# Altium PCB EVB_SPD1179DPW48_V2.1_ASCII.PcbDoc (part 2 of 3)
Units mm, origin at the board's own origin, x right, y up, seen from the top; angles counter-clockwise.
Board outline 135 x 90 mm, 4 copper layers (Top Layer, GND, L3, Bottom Layer), stack 0.603 mm thick; 322 components, 156 nets, 727 pads, 939 vias.
Unrouted connection lines stored in the file: 172.
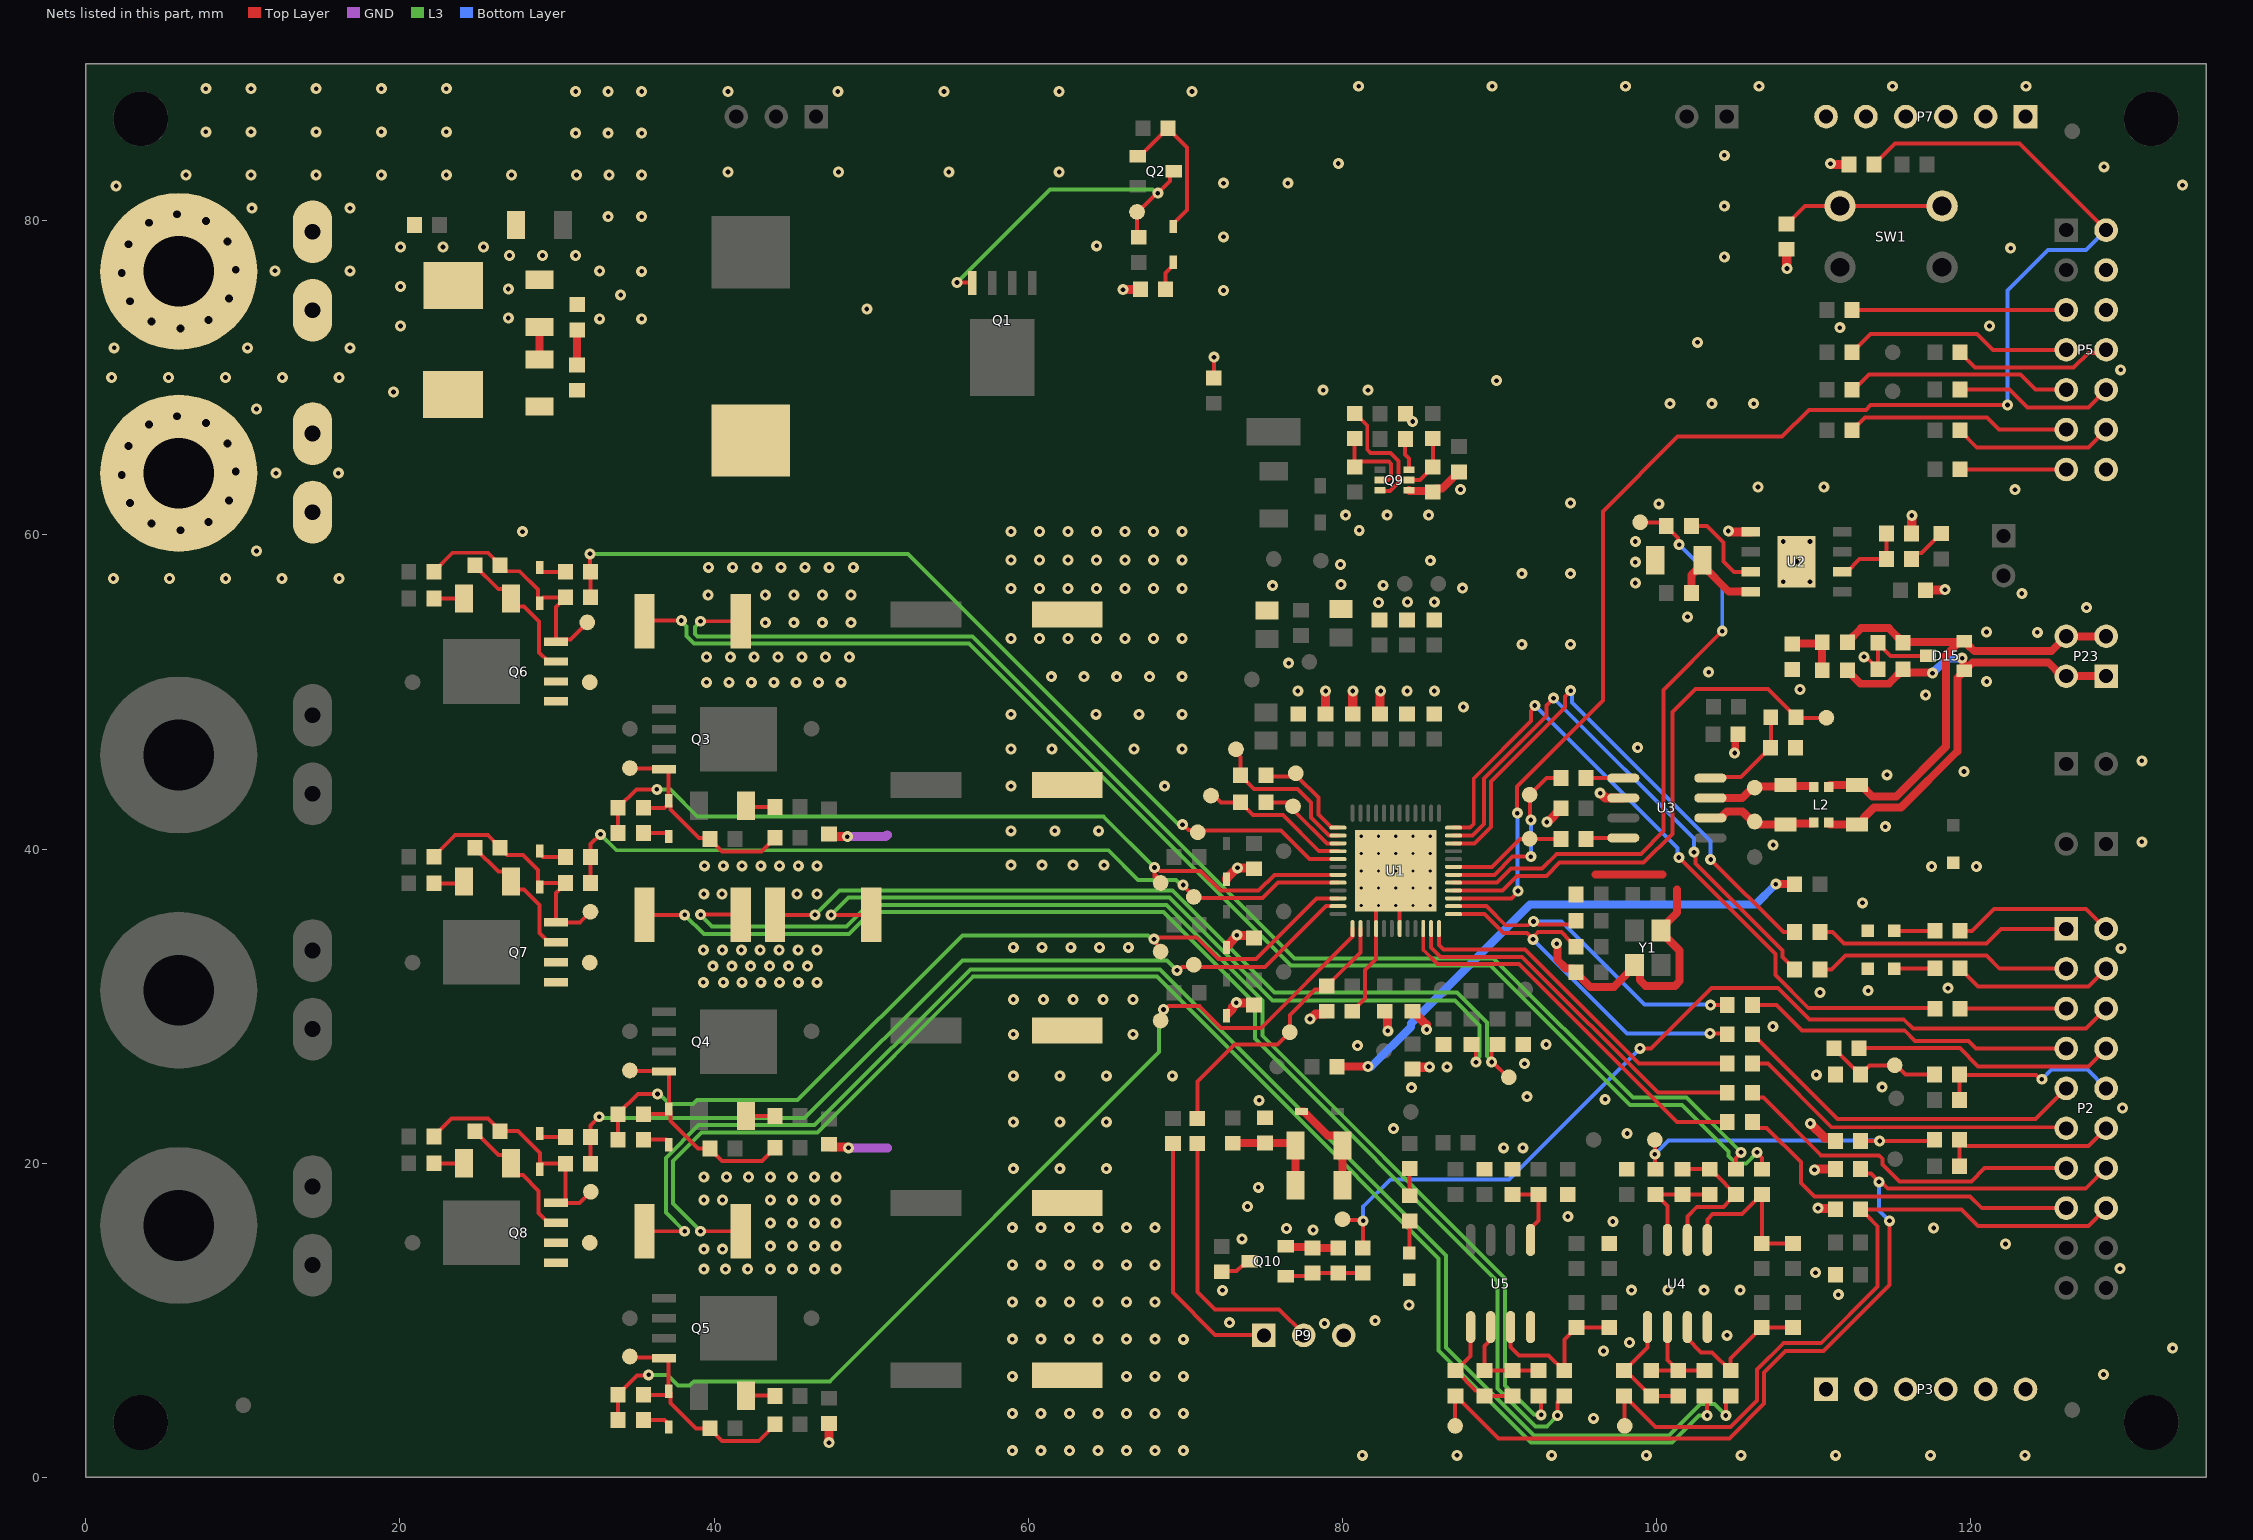
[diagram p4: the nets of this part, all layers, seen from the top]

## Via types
v1: diameter 0.7, hole 0.3, Top Layer to Bottom Layer, tented both sides, 693 vias
v2: diameter 0.5, hole 0.2, Top Layer to Bottom Layer, tented both sides, 154 vias
v3: diameter 0.9, hole 0.5, Top Layer to Bottom Layer, 60 vias
v4: diameter 0.5, hole 0.2, Top Layer to Bottom Layer, 32 vias

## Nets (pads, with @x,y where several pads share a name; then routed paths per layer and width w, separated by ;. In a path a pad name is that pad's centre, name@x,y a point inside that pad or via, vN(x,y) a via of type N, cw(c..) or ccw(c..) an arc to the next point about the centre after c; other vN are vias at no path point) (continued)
ADC0: R30.2 U1.46 | length 25.2
  Top Layer w0.254: U1.46@85.152,34.941 85.152,33.593 86.06,32.685 91.255,32.685 101.309,22.631 R30.2@104.508,22.631
ADC1: R29.2 U1.47 | length 23.9
  Top Layer w0.254: U1.47@85.652,34.941 85.652,33.74 86.249,33.142 91.445,33.142 100.095,24.492 R29.2@104.508,24.492
ADC2: R28.2 U1.48 | length 22.5
  Top Layer w0.254: U1.48@86.152,34.941 86.152,33.887 86.439,33.6 91.634,33.6 98.881,26.352 R28.2@104.508,26.352
ADC3: R1.2 R10.2 U1.1 | length 24
  Top Layer w0.254: U1.1@87.077,35.866 89.04,35.866 90.26,34.646 91.747,34.646 v1(92.135,34.258) 92.152,34.275 92.152,34.402 92.472,34.722 93.942,34.722 94.509,34.155 94.534,34.155 94.882,33.807 R1.2@94.882,33.782 ; v1(103.403,28.27) 104.451,28.27 R10.2@104.508,28.213
  Bottom Layer w0.254: v1(92.135,34.258) 98.122,28.27 v1(103.403,28.27)
ADC4: R8.2 R120.2 U1.2 | length 23.3
  Top Layer w0.254: U1.2@87.077,36.366 89.186,36.366 90.399,35.154 91.815,35.154 92.049,35.387 v1(92.17,35.387) ; v1@92.07,35.387 92.253,35.204 92.35,35.302 92.376,35.302 92.473,35.204 94.653,35.204 R120.2@94.882,35.433 ; v1(103.438,30.065) 104.5,30.065 R8.2@104.508,30.074
  Bottom Layer w0.254: v1(92.17,35.387) 93.95,35.387 99.238,30.099 103.403,30.099 v1(103.438,30.065)
BOOT: P5.2 R11.2 U1.3 | length 91.7
  Top Layer w0.254: U1.3@87.5,36.866 90.765,36.866 91.186,37.287 v1(91.186,37.332) ; v1(91.142,42.291) 91.118,42.315 91.118,43.989 96.585,49.456 96.585,61.509 101.344,66.269 108.001,66.269 109.703,67.97 113.334,67.97 113.639,68.275 v1(122.352,68.275) ; R11.2@113.855,83.591 115.194,84.93 123.106,84.93 P5.2@128.626,79.41
  Bottom Layer w0.254: v1(91.142,42.291) 91.142,37.376 v1(91.186,37.332) ; v1(122.352,68.275) 122.352,75.565 124.917,78.13 127.346,78.13 P5.2@128.626,79.41
CANH: CANH.1 L2.1 R59.1 U3.7 | length 7
  Top Layer w0.508: U3.7@103.433,43.256 105.455,43.256 106.194,43.995 108.13,43.995 L2.1@108.209,44.074 108.266,44.018 109.969,44.018 110.01,43.977 R59.1@110.01,43.961
CANL: CANL.1 L2.2 R67.1 U3.6 | length 6.8
  Top Layer w0.508: U3.6@103.433,41.986 104.14,41.986 104.177,42.023 104.177,42.07 104.499,42.393 105.48,42.393 106.115,41.758 CANL.1@106.248,41.758 ; CANL.1@106.564,41.575 L2.2@108.209,41.575 108.266,41.631 109.969,41.631 110.01,41.672 R67.1@110.01,41.688
CANLDOEN: CANLDOEN.1 R81.1 U1.5 | length 39
  Top Layer w0.254: U1.5@87.077,37.866 89.832,37.866 90.727,38.76 92.71,38.76 93.65,39.701 99.01,39.701 100.457,41.148 100.457,50.145 v1(104.188,53.876) ; CANLDOEN.1@98.958,60.808 100.394,60.808 R81.1@100.622,60.579 100.622,60.554 101.362,59.814 101.362,59.471 v1(101.448,59.385)
  Bottom Layer w0.254: v1(101.448,59.385) 104.188,56.645 v1(104.188,53.876)
CANRX: CANRX.1 R65.2 U1.7 | length 7.6
  Top Layer w0.254: U1.7@87.077,38.866 89.539,38.866 91.313,40.64 R65.2@93.917,40.64
CANSTB: CANSTB.1 R79.1 U1.4 | length 34.4
  Top Layer w0.254: U1.4@87.077,37.366 90.186,37.366 91.123,38.303 92.989,38.303 93.828,39.141 99.187,39.141 101.016,40.97 101.016,48.717 102.489,50.19 107.099,50.19 108.877,48.412 R79.1@108.877,48.387 108.902,48.362 CANSTB.1@110.82,48.362
CANTX: CANTX.1 R62.2 U1.6 | length 11.8
  Top Layer w0.254: U1.6@87.077,38.366 89.686,38.366 90.842,39.522 v1(91.999,39.522) ; v1(91.999,41.859) 91.961,41.897 91.961,43.396 91.91,43.447 92.989,44.526 R62.2@93.917,44.526
  Bottom Layer w0.254: v1(91.999,39.522) v1(91.999,41.859)
CFBOT0: C50.1 CFBOT0.1 U1.26 | length 10.1
  Top Layer w0.254: CFBOT0.1@73.228,46.355 73.228,46.153 73.53,45.852 C50.1@73.53,44.704 73.53,44.679 74.386,43.823 77.149,43.823 78.013,42.959 78.013,42.012 79.157,40.868 79.725,40.868 U1.26@79.727,40.866
CFBOT1: C45.2 CFBOT1.1 U1.28 | length 9.6
  Top Layer w0.254: CFBOT1.1@71.637,43.409 71.839,43.409 72.271,42.977 C45.2@73.53,42.977 73.53,42.952 74.31,42.172 76.222,42.172 78.528,39.866 U1.28@79.727,39.866
CFTOP0: C50.2 CFTOP0.1 U1.25 | length 6.6
  Top Layer w0.254: C50.2@75.13,44.704 75.206,44.628 77.124,44.628 78.47,43.282 78.47,42.202 79.306,41.366 U1.25@79.727,41.366
CFTOP1: C45.1 CFTOP1.1 U1.27 | length 5.8
  Top Layer w0.254: C45.1@75.13,42.977 76.602,42.977 77.059,42.52 77.003,42.464 77.003,42.375 79.01,40.368 79.725,40.368 U1.27@79.727,40.366
D2SOUT: P2.8 R122.2 | length 16.7
  Top Layer w0.254: R122.2@112.89,27.33 119.318,27.33 120.474,26.174 127.495,26.174 P2.8@128.626,27.305
FB: R56.1 R57.2 U2.2 | length 4.8
  Top Layer w0.254: U2.2@111.823,57.658 112.123,57.658 112.936,58.471 R56.1@114.643,58.471 R57.2@114.643,60.096
GND: C1.2 C2.1 C5.2 C6.2 C7.1 C8.1 C10.2 C11.1 C12.1 C13.1 C14.2 C15.2 C16.1 C17.1 C18.1 C19.1 C23.1 C24.1 C29.1 C30.1 C31.1 C32.1 C33.1 C34.1 C35.1 C36.1 C37.1 C38.1 C39.1 C40.1 C41.1 C44.1 C52.1 C53.1 C54.1 C55.1 C57.1 C58.1 C61.1 C62.1 C63.1 C64.1 C70.1 C71.1 C72.1 C73.1 C74.1 C77.1 C78.1 C80.1 C81.1 C83.1 C84.1 C90.1 D1.1 D3.2 D4.2 D5.2 D13.2 D14.2 D15.3 D17.2 D18.1 P3.1 P3.2 P3.3 P3.4 P3.5 P3.6 P5.4 P5.6 P5.14 P6.1 P7.1 P7.2 P7.3 P7.4 P7.5 P7.6 P9.3 pad.1@5.918,76.784 Q9.1 Q10.2 R7.1 R9.2 R11.1 R55.1 R57.1 R58.1 R61.1 R85.2 R94.1 R98.2 R99.1 R109.2 U1.40 U1.43 U1.49 U2.5 U2.9 U3.2 U4.4 U5.4 Y1.2 Y1.4 | length 139.4
  Top Layer w0.254: v1(47.459,35.808) 50,35.808 R55.1@50.005,35.814 ; R109.2@71.806,69.99 71.831,70.015 v1(71.831,71.323) ; C78.1@80.629,29.68 80.654,29.68 81.002,30.028 81.002,30.053 81.442,30.493 81.442,32.309 82.152,33.019 U1.40@82.152,34.941 82.152,36.266 v4(82.302,36.416) ; v4(83.402,36.416) 83.652,36.166 U1.43@83.652,34.941 ; R98.2@84.01,67.716 84.482,67.245 v1(84.482,67.22) ; R58.1@88.224,27.572 88.519,27.276 88.516,27.274 v1(88.516,26.44) ; v1(113.208,52.248) 113.293,52.162 113.42,52.162 C62.1@114.097,51.485 ; C62.1@114.097,51.46 C62.1@114.097,51.485 ; C54.1@114.097,53.137 C54.1@114.097,53.112 ; D15.3@117.29,52.299 114.91,52.299 C54.1@114.097,53.112 ; C62.1@114.097,51.485 C54.1@114.097,53.112
  Top Layer w0.508: Q10.2@76.403,14.719 76.46,14.662 78.048,14.662 C80.1@78.105,14.605 R94.1@79.731,14.605 ; Q9.1@84.232,62.85 84.276,62.806 85.687,62.806 R99.1@85.765,62.728 85.986,62.949 86.352,62.949 87.181,63.777 87.181,63.802 87.402,64.023 C83.1@87.427,64.023 ; v1(93.647,33.983) 93.684,33.946 93.684,32.96 94.242,32.402 94.661,32.402 94.882,32.181 C12.1@94.882,32.156 ; C12.1@94.882,32.131 95.789,31.225 97.284,31.225 98.591,32.531 Y1.4@98.591,32.631 98.937,32.285 98.937,31.67 99.314,31.293 101.175,31.293 101.473,31.59 101.473,33.549 100.291,34.731 Y1.2@100.291,34.831 100.291,34.931 101.321,35.961 101.321,37.438 ; C13.1@94.882,37.084 C13.1@94.882,37.109 C13.1@94.882,37.134 ; 96.127,38.379 100.379,38.379 ; v1(104.978,46.126) 105.015,46.163 105.015,47.141 C61.1@105.194,47.32
  Top Layer w0.58: v1(47.32,2.21) C18.1@47.32,3.442 ; C16.1@47.32,21.212 47.505,21.027 48.485,21.027 48.532,20.98 v1(48.565,20.98) ; C17.1@47.32,40.964 47.469,40.815 48.466,40.815 v1(48.489,40.792) ; v1(66.04,75.616) 66.053,75.629 67.132,75.629 R7.1@67.145,75.641 ; D5.2@72.628,38.078 72.628,38.148 73.269,38.788 73.307,38.788 v1(73.33,38.811) 73.353,38.788 74.343,38.788 C24.1@74.381,38.751 ; D3.2@72.688,29.521 73.011,29.843 73.011,29.951 73.254,30.194 v1(73.254,30.226) 73.277,30.203 74.242,30.203 C19.1@74.381,30.064 ; D4.2@72.688,33.864 73.011,34.187 73.011,34.218 73.279,34.486 v1(73.279,34.519) 73.302,34.496 74.239,34.496 C23.1@74.381,34.354 ; v1(77.947,29.185) 77.979,29.185 78.29,29.495 78.818,29.495 C8.1@79.003,29.68 ; C37.1@78.93,48.603 78.937,48.609 78.937,50.057 v1(78.943,50.063) ; C36.1@80.661,48.603 80.666,48.608 80.666,50.059 v1(80.67,50.063) ; C33.1@82.32,54.637 C33.1@82.372,54.585 ; C84.1@82.398,48.603 82.398,49.986 82.443,50.031 v1(82.443,50.063) ; C7.1@82.703,29.68 82.876,29.507 82.876,28.452 v1(82.899,28.429) ; C40.1@84.464,25.997 84.581,26.114 85.524,26.114 v1(85.547,26.137) ; C41.1@84.464,29.68 84.489,29.68 85.345,28.825 85.345,28.545 v1(85.368,28.522) ; v1(93.015,41.732) 93.038,41.755 93.101,41.755 93.917,42.571 C58.1@93.917,42.596 ; v1(96.418,43.561) 96.451,43.561 96.754,43.258 97.886,43.258 U3.2@97.888,43.256 ; v1(104.572,60.249) 104.604,60.249 104.655,60.198 U2.5@106.007,60.198 ; R9.2@108.28,78.194 108.293,78.181 108.293,76.975 v1(108.306,76.962) ; v1(109.796,22.534) 110.708,21.622 111.207,21.622 111.392,21.437 C63.1@111.392,21.412 ; v1(110.058,19.583) 110.091,19.583 110.141,19.634 C81.1@111.392,19.634 ; v1(110.287,17.145) 110.31,17.122 111.339,17.122 C64.1@111.392,17.069 ; v1(111.074,83.642) 111.107,83.642 111.157,83.591 R11.1@112.255,83.591 ; R57.1@116.243,60.096 116.249,60.103 116.249,61.233 v1(116.256,61.239) ; C44.1@117.132,56.49 117.145,56.502 118.351,56.502 v1(118.364,56.515)
  GND w0.58: v1(48.489,40.792) 50.927,40.792 51.029,40.894 ; v1(48.565,20.98) 51.054,20.98
  L3 w0.254: v1(47.459,35.808) 48.557,36.906 69.003,36.906 75.556,30.353 87.161,30.353 88.748,28.767 88.748,26.792 88.516,26.561 v1(88.516,26.44)
  other v1: 81.272,1.401 87.3,1.401 93.328,1.401 99.357,1.401 105.385,1.401 111.413,1.401 117.441,1.401 123.469,1.401 58.991,1.702 60.808,1.702 62.624,1.702 64.44,1.702 66.256,1.702 68.072,1.702 69.875,1.702 95.987,3.759 58.991,4.068 60.808,4.068 62.624,4.068 64.44,4.068 66.256,4.068 68.072,4.068 69.875,4.068 58.991,6.435 66.256,6.435 68.072,6.435 69.875,6.435 128.465,6.558 96.622,8.052 132.867,8.23 98.289,8.592 58.991,8.801 60.808,8.801 62.624,8.801 64.44,8.801 66.256,8.801 68.072,8.801 69.875,8.788 104.487,9.049 78.867,9.804 72.822,9.855 82.093,9.982 84.244,10.977 58.991,11.168 60.808,11.168 62.624,11.168 64.44,11.168 66.256,11.168 68.072,11.168 111.574,11.638 72.365,11.913 98.416,11.919 100.719,11.919 103.022,11.919 105.325,11.919 110.126,13.035 129.507,13.289 58.991,13.534 60.808,13.534 62.624,13.534 64.44,13.534 66.256,13.534 68.072,13.534 122.225,14.859 73.616,15.192 78.146,15.745 76.445,15.846 117.645,15.879 58.991,15.9 60.808,15.9 62.624,15.9 64.44,15.9 66.256,15.9 68.072,15.9 97.223,16.286 94.353,16.616 73.965,17.247 74.651,18.466 59.055,19.66 62.014,19.66 64.973,19.66 90.272,20.98 91.491,20.98 98.137,21.901 83.261,22.2 59.055,22.624 62.014,22.631 64.973,22.624 129.667,23.52 74.701,24.003 96.73,24.068 91.762,24.236 84.404,24.816 114.368,24.846 59.055,25.571 62.014,25.571 64.973,25.571 69.173,25.571 110.177,25.633 86.665,26.137 91.592,26.34 80.967,27.487 92.981,27.563 59.055,28.212 66.675,28.212 107.409,28.706 59.055,30.429 60.96,30.429 62.865,30.429 64.77,30.429 66.675,30.429 110.406,30.865 113.479,30.992 118.559,31.145 129.583,33.685 59.055,33.749 60.884,33.749 62.713,33.749 64.541,33.749 66.37,33.749 113.124,36.58 117.518,38.892 120.363,38.892 58.903,38.982 60.878,38.982 62.854,38.982 64.83,38.982 107.434,40.263 130.902,40.462 58.903,41.166 61.697,41.166 64.491,41.166 114.571,41.432 58.903,44.011 68.691,44.011 114.673,44.734 119.575,44.937 130.902,45.618 58.903,46.373 61.503,46.373 66.735,46.373 69.799,46.373 98.806,46.457 58.903,48.583 64.313,48.583 67.056,48.583 69.799,48.583 87.706,49.047 117.137,49.814 77.165,50.063 84.125,50.063 85.852,50.063 109.144,50.165 121.023,50.677 61.468,50.978 63.551,50.978 65.634,50.978 67.716,50.978 69.799,50.978 103.319,51.262 76.581,51.841 91.431,53.042 94.53,53.042 58.903,53.416 60.719,53.416 62.535,53.416 64.351,53.416 66.167,53.416 67.983,53.416 69.799,53.416 124.249,53.802 121.006,53.823 101.973,54.792 127.373,55.376 82.296,55.702 84.15,55.728 85.852,55.728 123.257,56.28 58.903,56.591 60.719,56.591 62.535,56.591 64.351,56.591 66.167,56.591 67.983,56.591 69.799,56.591 87.655,56.617 75.565,56.769 82.601,56.794 79.908,56.845 98.654,56.947 108.066,57.026 109.768,57.026 91.431,57.537 94.53,57.537 79.883,58.115 98.654,58.268 108.917,58.309 85.598,58.369 58.903,58.407 60.719,58.407 62.535,58.407 64.351,58.407 66.167,58.407 67.983,58.407 69.799,58.407 98.654,59.588 108.066,59.592 109.768,59.592 58.903,60.223 60.719,60.223 62.535,60.223 64.351,60.223 66.167,60.223 67.983,60.223 69.799,60.223 81.077,60.3 80.213,61.265 82.855,61.265 85.496,61.265 100.146,61.982 94.53,62.033 87.526,62.893 122.825,62.884 106.467,63.061 110.658,63.061 100.854,68.358 103.521,68.358 106.188,68.358 78.783,69.219 81.628,69.219 89.814,69.825 129.557,70.515 1.809,71.914 10.293,71.914 16.821,71.914 102.616,72.263 111.671,73.197 20.041,73.304 121.201,73.309 32.715,73.762 35.393,73.762 26.899,73.812 49.725,74.392 34.054,75.286 72.433,75.569 26.899,75.667 20.041,75.819 35.393,76.784 12.045,76.816 16.821,76.816 32.715,76.81 104.318,77.699 26.975,77.8 29.083,77.8 31.191,77.8 122.547,78.262 20.041,78.334 22.746,78.334 25.324,78.334 64.364,78.413 72.433,78.986 33.259,80.262 35.393,80.262 10.572,80.804 16.821,80.804 104.318,80.937 1.93,82.22 133.494,82.275 72.433,82.402 76.53,82.402 6.378,82.92 10.523,82.92 14.668,82.92 18.813,82.92 22.958,82.92 27.103,82.92 31.248,82.92 33.32,82.92 35.393,82.92 40.894,83.112 47.921,83.112 54.949,83.112 61.976,83.112 128.491,83.443 79.748,83.647 104.318,84.176 31.191,85.579 33.259,85.579 35.393,85.579 7.645,85.669 10.523,85.669 14.668,85.669 18.813,85.669 22.958,85.669 31.191,88.237 33.259,88.237 35.393,88.24 40.894,88.24 47.879,88.24 54.635,88.24 61.976,88.24 70.434,88.24 7.645,88.417 10.523,88.417 14.668,88.417 18.813,88.417 22.958,88.417 81.043,88.57 89.539,88.57 98.034,88.57 106.529,88.57 115.025,88.57 123.52,88.57
  other v3: 6.02,73.152 4.19,73.588 7.822,73.689 2.823,74.88 9.115,75.056 2.286,76.683 9.55,76.886 2.722,78.512 9.013,78.688 4.014,79.879 7.646,79.981 5.817,80.416
  other v4: 81.202,36.416 84.502,36.416 85.602,36.416 81.202,37.516 82.302,37.516 83.402,37.516 84.502,37.516 85.602,37.516 81.202,38.616 82.302,38.616 83.402,38.616 84.502,38.616 85.602,38.616 81.202,39.716 82.302,39.716 83.402,39.716 84.502,39.716 85.602,39.716 81.202,40.816 82.302,40.816 83.402,40.816 84.502,40.816 85.602,40.816
HO_U: HOU.1 R24.2 R27.2 U1.37 | length 64.3
  Top Layer w0.254: R24.2@33.896,3.658 R27.2@33.896,5.258 33.896,5.283 35.108,6.495 35.806,6.495 v1(35.839,6.528) ; HOU.1@68.428,29.083 HOU.1@68.428,29.285 ; v1(68.616,29.79) 68.737,29.79 68.944,29.997 70.901,29.997 72.272,28.626 74.838,28.626 80.652,34.44 U1.37@80.652,34.941
  L3 w0.254: v1(35.839,6.528) 37.022,6.528 37.712,5.837 38.425,5.837 38.71,6.121 47.371,6.121 68.342,27.093 68.342,29.418 68.616,29.692 v1(68.616,29.79)
HO_V: HOV.1 R23.2 R26.2 U1.34 | length 56
  Top Layer w0.254: R23.2@33.896,21.504 33.896,23.155 35.151,24.409 v1(36.398,24.409) ; HOV.1@68.428,33.477 68.428,33.679 68.091,34.016 68.091,34.18 v1(68.005,34.266) 68.126,34.266 68.235,34.374 70.731,34.374 72.111,32.995 74.498,32.995 78.37,36.866 U1.34@79.727,36.866
  L3 w0.254: v1(36.398,24.409) 36.519,24.409 37.154,23.774 38.659,23.774 38.913,24.028 45.325,24.028 55.807,34.51 67.64,34.51 67.885,34.266 v1(68.005,34.266)
HO_W: HOW.1 R22.2 R25.2 U1.31 | length 52.7
  Top Layer w0.254: R22.2@33.896,41.028 33.896,42.653 35.049,43.805 v1(36.357,43.805) ; HOW.1@68.428,37.846 HOW.1@68.285,37.989 ; U1.31@79.727,38.366 75.688,38.366 74.675,37.353 72.232,37.353 70.977,38.608 68.396,38.608 68.167,38.837 v1(68.047,38.837) 68.047,38.692 68.047,38.398 ; 68.047,38.398 68.132,38.312 68.285,38.159 HOW.1@68.285,37.989 ; 68.047,38.398 68.047,38.227 68.2,38.074 HOW.1@68.285,37.989
  L3 w0.254: v1(36.357,43.805) 36.378,43.785 37.215,43.785 38.937,42.062 64.805,42.062 68.03,38.837 v1(68.047,38.837)
IBS+: IBS+.1 R51.1 R52.1 R53.1 R54.1 R55.2 R70.2 R71.2 R89.2 | length 313.1
  Top Layer w0.254: v1(39.141,15.672) R53.1@41.7,15.672 ; v1(39.141,54.508) R51.1@41.7,54.508 ; v1(39.15,35.823) 41.691,35.823 R52.1@41.7,35.814 ; R55.2@43.873,35.814 v1(46.431,35.814) ; R54.1@89.875,27.572 89.854,27.572 89.506,27.224 89.506,26.445 v1(89.51,26.441) 89.573,26.441 90.538,25.476 IBS+.1@90.602,25.476 ; R89.2@92.491,5.194 92.659,5.026 v1(92.659,3.982) ; R71.2@103.057,5.194 103.226,5.026 v1(103.226,3.937) ; R70.2@105.057,19.621 105.057,20.346 105.385,20.674 v1(105.385,20.701)
  L3 w0.254: v1(39.141,15.672) 39.141,15.69 37.389,17.442 37.389,20.156 39.204,21.971 46.595,21.971 56.501,31.877 68.195,31.877 75.77,24.302 86.131,13.941 86.131,8.091 92.009,2.213 100.994,2.213 102.709,3.928 103.217,3.928 v1(103.226,3.937) ; v1(39.141,54.508) 39.141,54.492 38.786,54.137 38.786,53.692 38.935,53.543 56.464,53.543 76.962,33.045 89.637,33.045 98.501,24.181 101.905,24.181 v1(105.385,20.701) ; v1(39.15,35.823) 39.15,35.805 39.878,35.077 48.426,35.077 49.798,36.449 68.813,36.449 74.903,30.359 74.903,28.119 90.348,12.675 90.348,5.842 92.193,3.997 92.645,3.997 v1(92.659,3.982) ; v1(46.431,35.814) 47.981,37.363 69.192,37.363 75.694,30.861 87.3,30.861 89.205,28.956 89.205,26.813 89.51,26.508 v1(89.51,26.441)
  other v1: 39.345,13.259 40.729,13.259 42.139,13.259 43.586,13.259 44.983,13.259 46.38,13.259 47.777,13.259 39.345,14.529 40.538,14.529 43.586,14.726 44.983,14.726 46.38,14.726 47.777,14.726 43.586,16.192 44.983,16.192 46.38,16.192 47.777,16.192 39.345,17.659 40.538,17.659 43.586,17.659 44.983,17.659 46.38,17.659 47.777,17.659 39.345,19.126 40.792,19.126 42.189,19.126 43.586,19.126 44.983,19.126 46.38,19.126 47.777,19.126 39.319,31.521 40.589,31.521 41.783,31.521 42.977,31.521 44.171,31.521 45.364,31.521 46.558,31.521 39.922,32.55 41.129,32.55 42.335,32.55 43.542,32.55 44.748,32.55 45.955,32.55 39.319,33.579 40.526,33.579 41.732,33.579 42.939,33.579 44.145,33.579 45.352,33.579 46.558,33.579 39.345,37.141 40.509,37.141 45.284,37.141 46.558,37.141 39.395,38.938 40.589,38.938 41.783,38.938 42.977,38.938 44.171,38.938 45.364,38.938 46.558,38.938 39.522,50.622 40.949,50.622 42.376,50.622 43.802,50.622 45.229,50.622 46.656,50.622 48.082,50.622 39.522,52.229 41.038,52.229 42.553,52.229 44.069,52.229 45.585,52.229 47.1,52.229 48.616,52.229 43.26,54.413 45.077,54.413 46.895,54.413 48.713,54.413 39.624,56.185 43.26,56.185 45.077,56.185 46.895,56.185 48.713,56.185 39.645,57.944 41.182,57.944 42.718,57.944 44.255,57.944 45.792,57.944 47.328,57.944 48.865,57.944
IDC: C90.2 IDC.1 R86.1 R122.1 | length 7.5
  Top Layer w0.254: R122.1@111.29,27.33 111.29,27.305 112.569,26.027 112.644,26.027 C90.2@112.992,25.679 ; IDC.1@115.164,26.238 113.576,26.238 113.365,26.027 113.34,26.027 C90.2@112.992,25.679 ; IDC.1@115.292,26.213 115.851,25.654 R86.1@117.704,25.654 ; C90.2@112.992,25.679 C90.2@112.992,25.654 C90.2@112.992,25.679
IO12: R3.2 U1.10 | length 35.3
  Top Layer w0.254: U1.10@87.077,40.366 88.421,40.366 89.47,41.416 89.47,44.309 94.183,49.022 94.183,49.717 94.539,50.073 v1(94.539,50.089) ; v1(103.454,39.345) 108.077,34.722 R3.2@108.801,34.722
  Bottom Layer w0.254: v1(94.539,50.089) 94.624,50.003 94.624,49.343 103.454,40.513 v1(103.454,39.345)
IO13: R2.2 U1.11 | length 35.7
  Top Layer w0.254: U1.11@87.077,40.866 88.274,40.866 89.013,41.605 89.013,44.499 92.989,48.475 92.989,49.149 v1(93.447,49.606) ; v1(102.385,39.803) 102.47,39.718 102.47,39.089 108.026,33.533 108.026,33.134 108.801,32.359 R2.2@108.801,32.334
  Bottom Layer w0.254: v1(93.447,49.606) 102.385,40.668 v1(102.385,39.803)
IO14: R6.2 U1.12 | length 45.1
  Top Layer w0.254: U1.12@87.077,41.366 88.127,41.366 88.367,41.605 88.367,44.499 92.024,48.156 92.024,48.794 92.258,49.028 v1(92.258,49.149) ; v1(101.422,39.472) 107.569,33.325 107.569,31.979 109.678,29.87 R6.2@117.729,29.87
  Bottom Layer w0.254: v1(92.258,49.149) 101.337,40.071 101.337,39.557 v1(101.422,39.472)
IU: C64.2 IU.1 P2.16 R73.1 | length 45.7
  Top Layer w0.254: R73.1@97.935,5.194 97.974,5.155 IU.1@97.974,3.277 ; R73.1@97.96,5.194 99.948,3.206 104.722,3.206 106.401,4.884 106.401,6.858 108.102,8.56 110.49,8.56 114.071,12.141 114.071,15.989 113.365,16.696 113.34,16.696 112.992,17.044 C64.2@112.992,17.069 119.42,17.069 120.474,16.014 127.495,16.014 P2.16@128.626,17.145
IUS+: C48.1 Q8.1 Q8.2 Q8.3 R47.2 R53.2 R75.2 S.1@32.08,14.935 | length 107.1
  Top Layer w0.254: C48.1@24.778,22.047 24.778,22.022 26.271,20.529 26.63,20.529 27.302,19.857 27.302,19.462 27.526,19.238 27.824,19.238 28.829,18.234 28.829,16.821 29.445,16.205 Q8.3@29.94,16.205 ; R53.2@35.567,15.672 v1(38.125,15.672) ; v1(104.419,3.937) 104.419,4.889 R75.2@104.725,5.194
  L3 w0.254: v1(38.125,15.672) 36.932,16.866 36.932,20.345 39.014,22.428 46.406,22.428 56.312,32.334 68.384,32.334 86.589,14.13 86.589,8.28 92.198,2.671 100.805,2.671 102.802,4.668 103.688,4.668 v1(104.419,3.937)
IV: C81.2 IV.1 P2.14 R90.1 | length 59.4
  Top Layer w0.254: IV.1@87.182,3.277 87.182,5.169 R90.1@87.208,5.194 87.233,5.194 89.955,2.472 104.635,2.472 106.858,4.695 106.858,6.669 108.227,8.038 110.633,8.038 114.833,12.239 v1(114.833,16.338) ; C81.2@112.992,19.634 113.288,19.338 113.656,19.338 v1(114.173,18.821) 114.294,18.821 114.725,18.39 127.33,18.39 P2.14@128.626,19.685
  Bottom Layer w0.254: v1(114.173,18.821) 114.173,16.998 v1(114.833,16.338)
IVS+: C47.1 Q7.1 Q7.2 Q7.3 R46.2 R52.2 R92.2 S.1@32.08,32.779 | length 88.7
  Top Layer w0.254: C47.1@24.778,40.08 24.778,40.055 26.271,38.562 26.63,38.562 27.078,38.114 27.078,37.866 27.526,37.418 27.885,37.418 28.873,36.43 28.873,34.646 29.445,34.074 Q7.3@29.94,34.074 ; R52.2@35.567,35.814 v1(38.125,35.814) ; v1(93.701,3.937) 93.701,4.762 93.76,4.821 93.76,4.846 94.108,5.194 R92.2@94.133,5.194
  L3 w0.254: v1(38.125,35.814) 39.345,34.595 48.59,34.595 49.987,35.992 68.624,35.992 74.446,30.169 74.446,27.93 89.891,12.485 89.891,5.653 92.292,3.251 93.015,3.251 v1(93.701,3.937)
IW: C63.2 IW.1 R72.1 R103.1 | length 21.3
  Top Layer w0.254: IW.1@99.898,21.488 v1(99.898,20.574) 99.898,19.658 R72.1@99.935,19.621 ; C63.2@112.992,21.412 v1(114.208,21.412) 117.627,21.412 R103.1@117.704,21.488
  Bottom Layer w0.254: v1(99.898,20.574) 100.762,21.438 114.183,21.438 v1(114.208,21.412)
IWS+: C46.1 Q6.1 Q6.2 Q6.3 R45.2 R51.2 R74.2 S.1@32.08,50.622 | length 96.4
  Top Layer w0.254: C46.1@24.778,58.064 24.778,58.039 26.271,56.547 26.63,56.547 27.302,55.875 27.302,55.676 27.526,55.452 27.885,55.452 28.854,54.483 28.854,52.534 29.445,51.943 Q6.3@29.94,51.943 ; R51.2@35.357,54.559 v1(37.915,54.559) ; v1(106.401,20.701) 106.401,20.671 106.725,20.346 R74.2@106.725,19.621
  L3 w0.254: v1(37.915,54.559) 37.915,54.525 38.252,54.187 38.252,53.569 38.735,53.086 56.242,53.086 76.74,32.588 89.447,32.588 98.312,23.724 101.625,23.724 104.597,20.752 104.597,20.455 105.082,19.97 105.687,19.97 106.401,20.683 v1(106.401,20.701)
KL30: C3.2 C4.2 D1.2 L1.1 P1.1 pad.1@5.918,63.932
  other v1: 1.753,57.226 5.328,57.226 8.903,57.226 12.478,57.226 16.129,57.226 10.871,58.979 27.802,60.211 12.116,63.932 16.078,63.932 10.871,68.021 19.597,69.101 1.651,70.028 5.271,70.028 8.89,70.028 12.509,70.028 16.129,70.028
  other v3: 6.02,60.3 4.19,60.735 7.822,60.837 2.823,62.028 9.115,62.204 2.286,63.83 9.55,64.033 2.722,65.66 9.013,65.836 4.014,67.027 7.646,67.128 5.817,67.564
LO_U: LOU.1 R36.2 R42.2 U1.35 | length 56.5
  Top Layer w0.254: R42.2@32.144,19.972 32.144,22.415 v1(32.69,22.962) ; v1(69.469,32.283) 69.59,32.283 69.803,32.496 70.402,32.496 LOU.1@70.545,32.639 70.686,32.498 75.078,32.498 78.946,36.366 U1.35@79.727,36.366
  L3 w0.254: v1(32.69,22.962) 32.766,22.885 45.771,22.885 55.804,32.918 68.834,32.918 v1(69.469,32.283)
LO_V: LOV.1 R35.2 R41.2 U1.32 | length 52.4
  Top Layer w0.254: R41.2@32.144,37.845 32.144,40.322 v1(32.766,40.945) ; v1(69.869,37.72) 69.869,37.677 70.545,37.001 LOV.1@70.545,36.957 70.607,36.896 74.929,36.896 75.899,37.866 U1.32@79.727,37.866
  L3 w0.254: v1(32.766,40.945) 33.782,39.929 65.126,39.929 67.005,38.049 69.419,38.049 69.748,37.72 v1(69.869,37.72)
LO_W: LOW.1 R34.2 R40.2 U1.29 | length 58.5
  Top Layer w0.254: v1(32.106,58.801) 32.106,57.696 R34.2@32.144,57.658 R40.2@32.144,56.032 ; v1(69.83,41.56) 69.864,41.56 70.21,41.215 70.606,41.215 70.621,41.199 76.082,41.199 77.915,39.366 U1.29@79.727,39.366
  L3 w0.254: v1(32.106,58.801) 52.349,58.801 69.505,41.645 69.745,41.645 v1(69.83,41.56)
MCU_FG: MCUFG.1 P2.6 R91.2 | length 58.7
  Top Layer w0.254: MCUFG.1@80.01,16.434 80.061,16.383 81.28,16.383 v1(81.331,16.332) 81.331,14.63 R91.2@81.305,14.605 ; v1(98.948,27.32) 99.659,27.32 103.505,31.166 107.735,31.166 109.742,29.159 115.742,29.159 116.327,28.575 127.356,28.575 P2.6@128.626,29.845
  Bottom Layer w0.254: v1(81.331,16.332) 81.331,17.247 83.058,18.974 90.602,18.974 v1(98.948,27.32)
MON: C8.2 MON.1 R78.1 U1.38 | length 18.3
  Top Layer w0.254: R78.1@70.764,22.847 70.764,25.197 73.127,27.559 75.87,27.559 MON.1@76.657,28.346 76.657,29.439 78.271,31.053 78.776,31.053 C8.2@79.003,31.28 79.028,31.28 79.376,31.628 79.376,31.653 81.152,33.428 U1.38@81.152,34.941
NetC2_2: C2.2 C3.1 | length 2.1
  Top Layer w0.508: C3.1@28.88,71.172 C2.2@28.88,73.252
NetC4_1: C4.1 C34.2 | length 2.3
  Top Layer w0.508: C4.1@31.267,70.815 31.28,70.828 31.28,73.05 C34.2@31.293,73.063
NetC9_1: C9.1 D2.1 Q2.1 | length 9.8
  Top Layer w0.254: Q2.1@66.973,84.11 67.098,84.11 68.518,85.53 68.549,85.53 C9.1@68.897,85.878 ; C9.1@68.897,85.903 C9.1@68.897,85.878 ; D2.1@69.24,79.648 69.24,79.838 70.103,80.701 70.103,84.673 C9.1@68.897,85.878
NetC20_1: C20.1 R32.1 | length 1.9
  Top Layer w0.254: R32.1@42.038,42.755 42.115,42.679 C20.1@43.879,42.679
NetC21_1: C21.1 R33.1 | length 1.8
  Top Layer w0.254: R33.1@42.038,23.003 C21.1@43.879,23.003
NetC22_1: C22.1 R37.1 | length 1.9
  Top Layer w0.254: R37.1@42.038,5.207 43.853,5.207 C22.1@43.879,5.182
NetC25_1: C25.1 R45.1 | length 1.9
  Top Layer w0.254: C25.1@22.161,55.956 R45.1@24.078,55.956
NetC26_2: C26.2 C56.2 D6.2 G.1@34.646,45.161 Q3.4 R25.1 | length 14.9
  Top Layer w0.254: G.1@34.646,45.161 34.68,45.126 36.77,45.126 Q3.4@36.805,45.092 36.97,45.092 37.109,44.952 D6.2@37.109,43.082 D6.2@37.109,42.892 ; R25.1@35.496,42.628 36.845,42.628 D6.2@37.109,42.892 ; C56.2@43.879,40.723 43.879,40.698 43.023,39.842 40.518,39.842 39.711,40.649 39.711,40.699 39.031,40.699 37.212,42.518 37.212,42.789 D6.2@37.109,42.892
NetC27_2: C27.2 C68.2 D7.2 G.1@34.646,25.908 Q4.4 R26.1 | length 15.3
  Top Layer w0.254: G.1@34.646,25.908 34.678,25.876 36.772,25.876 Q4.4@36.805,25.843 36.99,25.843 37.129,25.703 37.129,23.477 D7.2@37.109,23.457 ; R26.1@35.496,23.13 36.972,23.13 37.109,23.267 D7.2@37.109,23.354 ; D7.2@37.212,23.267 37.212,22.697 38.964,20.946 C27.2@39.738,20.946 39.738,20.921 40.518,20.141 43.048,20.141 43.879,20.971 C68.2@43.879,20.996
NetC28_2: C28.2 C69.2 D8.2 G.1@34.646,7.696 Q5.4 R27.1 | length 15.2
  Top Layer w0.254: G.1@34.646,7.696 34.696,7.645 36.754,7.645 Q5.4@36.805,7.595 36.97,7.595 37.109,7.455 D8.2@37.109,5.483 ; R27.1@35.496,5.258 37.006,5.258 37.109,5.361 D8.2@37.109,5.483 ; C69.2@43.879,3.378 43.879,3.353 42.845,2.319 40.518,2.319 39.738,3.099 C28.2@39.738,3.124 38.837,3.124 37.212,4.748 37.212,5.38 D8.2@37.109,5.483
NetC42_1: C42.1 R46.1 | length 2
  Top Layer w0.254: C42.1@22.161,37.819 23.951,37.819 R46.1@24.078,37.946
NetC43_1: C43.1 R47.1 | length 1.9
  Top Layer w0.254: C43.1@22.161,19.998 R47.1@24.078,19.998
NetC46_2: C46.2 C75.2 D9.2 G.1@31.928,54.432 Q6.4 R40.1 | length 16.3
  Top Layer w0.254: C75.2@22.161,57.658 22.161,57.683 23.348,58.869 25.598,58.869 26.378,58.089 C46.2@26.378,58.064 26.378,58.039 26.726,57.691 27.627,57.691 28.802,56.516 28.802,55.947 D9.2@28.905,55.844 ; D9.2@28.905,55.654 D9.2@28.905,55.844 ; G.1@31.928,54.432 30.848,53.353 30.08,53.353 Q6.4@29.94,53.213 29.94,55.404 30.544,56.007 R40.1@30.544,56.032 29.093,56.032 D9.2@28.905,55.844
NetC47_2: C47.2 C76.2 D10.2 G.1@32.131,36.017 Q7.4 R41.1 | length 16.2
  Top Layer w0.254: C76.2@22.161,39.521 22.161,39.546 23.5,40.885 25.598,40.885 26.378,40.105 C47.2@26.378,40.08 ; C47.2@26.378,40.055 26.809,39.624 27.838,39.624 28.802,38.66 D10.2@28.802,37.7 ; D10.2@28.905,37.597 28.905,37.742 29.008,37.845 R41.1@30.544,37.845 30.544,37.82 29.94,37.216 Q7.4@29.94,35.344 31.458,35.344 G.1@32.131,36.017
NetC48_2: C48.2 C79.2 D11.2 G.1@32.156,18.186 Q8.4 R42.1 | length 16
  Top Layer w0.254: C79.2@22.161,21.7 22.161,21.725 23.289,22.852 25.598,22.852 26.378,22.072 C48.2@26.378,22.047 27.508,22.047 28.905,20.65 D11.2@28.905,19.81 ; D11.2@28.905,19.62 D11.2@28.905,19.81 ; Q8.4@29.94,17.475 Q8.4@30.404,17.475 ; G.1@32.156,18.186 31.445,17.475 Q8.4@30.404,17.475 ; D11.2@28.905,19.81 29.068,19.972 R42.1@30.544,19.972 30.544,17.615 Q8.4@30.404,17.475
NetC54_2: C54.2 D15.2 L2.4 P23.3 P23.4 R59.2 R60.2 | length 33.6
  Top Layer w0.508: R59.2@110.97,43.961 110.97,43.986 111.058,44.074 L2.4@112.771,44.074 113.021,44.074 113.737,43.358 115.265,43.358 118.44,46.533 118.44,52.349 D15.2@119.193,53.103 ; R60.2@112.154,53.162 112.154,53.187 113.035,54.069 114.79,54.069 115.697,53.162 C54.2@115.697,53.137 115.753,53.193 119.534,53.193 D15.2@119.59,53.249 ; D15.2@119.836,53.003 120.235,52.603 125.136,52.603 P23.4@126.086,53.553 P23.3@128.626,53.553
NetC55_2: C55.2 R49.2 U2.8 | length 6.2
  Top Layer w0.508: R49.2@102.222,56.312 102.222,57.451 102.52,57.749 102.601,57.749 C55.2@102.922,58.07 ; C55.2@102.922,58.395 C55.2@102.922,58.07 ; U2.8@106.007,56.388 104.604,56.388 C55.2@102.922,58.07
NetC57_2: C57.2 R60.1 R63.1 | length 3.7
  Top Layer w0.508: C57.2@108.636,53.048 108.693,53.105 110.496,53.105 R60.1@110.554,53.162 R63.1@110.554,51.384
NetC59_1: C59.1 R68.1 R73.2 U4.1 | length 7.5
  Top Layer w0.254: U4.1@99.427,9.572 99.427,8.261 97.96,6.794 R73.2@97.935,6.794 98.283,6.446 98.385,6.446 99.637,5.194 C59.1@99.662,5.194 R68.1@101.389,5.194
NetC59_2: C59.2 R68.2 R71.1 U4.2 | length 6.4
  Top Layer w0.254: C59.2@99.662,6.794 R68.2@101.364,6.794 ; U4.2@100.697,9.572 100.697,7.462 R68.2@101.364,6.794 ; R71.1@103.057,6.794 R68.2@101.389,6.794 R68.2@101.364,6.794
NetC60_1: C60.1 R69.1 R72.2 U4.7 | length 6.7
  Top Layer w0.254: R72.2@99.935,18.021 R72.2@99.96,18.021 ; U4.7@100.697,15.117 100.697,17.284 R72.2@99.96,18.021 ; R69.1@103.389,18.021 C60.1@101.662,18.021 R72.2@99.96,18.021
NetC60_2: C60.2 R69.2 R70.1 U4.6 | length 9.2
  Top Layer w0.254: C60.2@101.662,19.621 R69.2@103.389,19.621 103.737,19.273 103.78,19.273 R70.1@105.032,18.021 ; U4.6@101.967,15.117 101.967,16.623 102.565,17.221 104.257,17.221 104.684,17.648 104.684,17.673 R70.1@105.032,18.021 ; R70.1@105.057,18.021 R70.1@105.032,18.021
NetC62_2: C62.2 D15.1 L2.3 P23.1 P23.2 R63.2 R67.2 | length 33.7
  Top Layer w0.508: R67.2@110.97,41.688 110.97,41.663 111.058,41.575 L2.3@112.771,41.575 113.021,41.575 113.217,41.77 113.217,42.02 113.843,42.647 115.57,42.647 119.151,46.228 119.151,50.905 D15.1@119.344,51.098 ; R63.2@112.154,51.384 112.154,51.359 112.984,50.529 114.79,50.529 115.697,51.435 C62.2@115.697,51.46 ; C62.2@115.918,51.228 115.918,51.243 117.54,51.243 v1(117.577,51.206) ; v1(119.465,52.161) 119.502,52.124 119.502,51.437 D15.1@119.59,51.349 ; D15.1@119.836,51.595 120.134,51.892 124.938,51.892 125.817,51.013 P23.1@128.626,51.013
  Bottom Layer w0.508: v1(117.577,51.206) 118.494,52.124 119.428,52.124 v1(119.465,52.161) v1@119.434,52.191
NetC65_2: C65.2 R74.1 R76.2 U4.5 | length 10.6
  Top Layer w0.254: U4.5@103.237,15.117 103.237,16.42 103.581,16.764 105.443,16.764 106.7,18.021 R74.1@106.725,18.021 106.705,18.002 R76.2@106.705,14.897 C65.2@108.687,14.897
NetC66_2: C66.2 R75.1 R77.2 U4.3 | length 9.9
  Top Layer w0.254: U4.3@101.967,9.572 101.967,8.843 102.849,7.961 103.534,7.961 104.7,6.794 R75.1@104.725,6.794 104.725,7.582 106.68,9.538 R77.2@106.705,9.538 C66.2@108.687,9.538
NetC67_1: C67.1 R80.1 R90.2 U5.1 | length 7.5
  Top Layer w0.254: R90.2@87.208,6.794 R90.2@87.233,6.794 ; U5.1@88.173,9.572 88.173,7.735 R90.2@87.233,6.794 ; R80.1@90.84,5.194 C67.1@89.057,5.194 88.709,5.542 88.485,5.542 R90.2@87.233,6.794
NetC67_2: C67.2 R80.2 R89.1 U5.2 | length 6.4
  Top Layer w0.254: U5.2@89.443,9.572 89.443,8.753 89.057,8.367 C67.2@89.057,6.794 R80.2@90.84,6.794 R89.1@92.491,6.794
NetC77_2: C77.2 R4.1 R83.1 R111.2 | length 6.4
  Top Layer w0.508: R111.2@73.025,21.273 73.038,21.285 75.07,21.285 C77.2@75.082,21.298 R83.1@76.846,21.298 ; R4.1@77.011,18.593 R83.1@77.011,21.133
NetC80_2: C80.2 Q10.1 R91.1 R94.2 | length 5
  Top Layer w0.254: Q10.1@76.403,12.819 77.919,12.819 C80.2@78.105,13.005 R94.2@79.731,13.005 R91.1@81.305,13.005
NetC82_2: C82.2 R92.1 R95.2 U5.3 | length 10.5
  Top Layer w0.254: U5.3@90.713,9.572 90.713,8.296 91.237,7.772 93.13,7.772 94.108,6.794 R92.1@94.133,6.794 94.133,8.792 94.879,9.538 R95.2@94.904,9.538 C82.2@96.987,9.538
NetD2_2: D2.2 R7.2 | length 1.9
  Top Layer w0.254: R7.2@68.745,75.641 68.745,76.683 69.24,77.178 D2.2@69.24,77.368
NetD6_1: D6.1 R22.1 | length 1.8
  Top Layer w0.254: R22.1@35.496,41.028 37.006,41.028 37.109,40.925 D6.1@37.109,40.802
NetD7_1: D7.1 R23.1 | length 1.9
  Top Layer w0.254: R23.1@35.496,21.504 36.972,21.504 37.109,21.367 D7.1@37.109,21.177
NetD8_1: D8.1 R24.1 | length 1.9
  Top Layer w0.254: R24.1@35.496,3.658 36.845,3.658 37.109,3.393 D8.1@37.109,3.203
NetD9_1: D9.1 R34.1 | length 1.9
  Top Layer w0.254: D9.1@28.905,57.934 28.905,57.761 29.008,57.658 R34.1@30.544,57.658
NetD10_1: D10.1 R35.1 | length 1.9
  Top Layer w0.254: D10.1@28.905,39.877 28.905,39.687 29.096,39.496 R35.1@30.544,39.496
NetD11_1: D11.1 R36.1 | length 1.8
  Top Layer w0.254: D11.1@28.905,21.9 28.905,21.777 29.008,21.674 R36.1@30.544,21.674
NetD13_1: D13.1 R102.2 | length 2.6
  Top Layer w0.254: D13.1@115.151,32.385 115.176,32.41 R102.2@117.729,32.41
NetD14_1: D14.1 R101.2 | length 2.6
  Top Layer w0.254: D14.1@115.176,34.798 R101.2@117.729,34.798
NetD16_1: D16.1 R4.2 R83.2 | length 6.2
  Top Layer w0.508: D16.1@77.406,23.292 77.548,23.292 79.061,21.779 79.69,21.779 80.011,21.458 R83.2@80.011,21.133 R4.2@80.011,18.593
NetD17_1: D17.1 R105.2 | length 2.1
  Top Layer w0.254: D17.1@84.261,14.287 84.287,14.313 R105.2@84.287,16.332
NetP2_1: P2.1 R3.1 | length 16.4
  Top Layer w0.254: R3.1@110.401,34.722 111.214,34.722 111.943,33.993 121.014,33.993 121.945,34.925 P2.1@126.086,34.925
NetP2_2: P2.2 R101.1 | length 10.4
  Top Layer w0.254: R101.1@119.329,34.798 120.088,34.798 121.485,36.195 127.356,36.195 P2.2@128.626,34.925
NetP2_3: P2.3 R2.1 | length 16.4
  Top Layer w0.254: R2.1@110.401,32.334 111.15,32.334 112.031,33.215 121.023,33.215 121.853,32.385 P2.3@126.086,32.385
NetP2_4: P2.4 R102.1 | length 10.3
  Top Layer w0.254: R102.1@119.329,32.41 119.329,32.385 120.46,31.254 127.495,31.254 P2.4@128.626,32.385
NetP2_5: P2.5 R6.1 | length 6.8
  Top Layer w0.254: R6.1@119.329,29.845 P2.5@126.086,29.845
NetP2_7: P2.7 R8.1 | length 21.1
  Top Layer w0.254: R8.1@106.108,30.074 107.645,30.074 109.271,28.448 115.807,28.448 116.467,27.788 119.863,27.788 120.345,27.305 P2.7@126.086,27.305
NetP2_9: P2.9 R10.1 | length 23
  Top Layer w0.254: R10.1@106.108,28.213 106.108,28.188 106.456,27.84 106.481,27.84 111.512,22.809 124.13,22.809 P2.9@126.086,24.765
NetP2_10: P2.10 R86.2 R87.2 | length 11.8
  Top Layer w0.254: R87.2@119.304,24.028 R86.2@119.304,25.629 ; R86.2@119.304,25.654 R86.2@119.304,25.629 ; v1(124.536,25.349) 124.444,25.349 124.164,25.629 R86.2@119.304,25.629
  Bottom Layer w0.254: v1(124.536,25.349) 125.146,25.959 127.432,25.959 P2.10@128.626,24.765
NetP2_11: P2.11 R28.1 | length 21.7
  Top Layer w0.254: R28.1@106.108,26.352 107.091,26.352 111.15,22.293 126.017,22.293 P2.11@126.086,22.225
NetP2_12: P2.12 R103.2 R104.2 | length 11.6
  Top Layer w0.254: R104.2@119.304,19.812 R103.2@119.304,21.488 119.304,21.463 119.652,21.115 119.779,21.115 119.8,21.094 127.495,21.094 P2.12@128.626,22.225
NetP2_13: P2.13 R29.1 | length 22.9
  Top Layer w0.254: R29.1@106.108,24.492 106.418,24.183 106.805,24.183 110.49,20.498 114.173,20.498 114.384,20.287 114.384,19.936 115.473,18.847 120.05,18.847 120.888,19.685 P2.13@126.086,19.685
NetP2_15: P2.15 R30.1 | length 23
  Top Layer w0.254: R30.1@106.108,22.631 106.108,22.606 106.456,22.258 107.002,22.258 109.188,20.073 109.188,18.752 110.053,17.887 119.968,17.887 120.71,17.145 P2.15@126.086,17.145
NetP5_5: P5.5 R13.1 | length 13.6
  Top Layer w0.254: R13.1@112.458,74.32 112.468,74.33 P5.5@126.086,74.33
NetP5_7: P5.7 R14.1 | length 14.5
  Top Layer w0.254: R14.1@112.458,71.628 112.458,71.653 112.806,72.001 112.831,72.001 113.627,72.796 120.421,72.796 121.428,71.79 P5.7@126.086,71.79
NetP5_8: P5.8 R15.2 | length 10.2
  Top Layer w0.254: R15.2@119.329,71.628 119.329,71.603 120.269,70.663 123.41,70.663 123.414,70.659 126.554,70.659 127.495,71.599 128.435,71.599 P5.8@128.626,71.79
NetP5_9: P5.9 R16.1 | length 14.5
  Top Layer w0.254: R16.1@112.458,69.147 112.458,69.172 112.806,69.52 112.831,69.52 113.517,70.206 123.19,70.206 124.146,69.25 P5.9@126.086,69.25
NetP5_10: P5.10 R17.2 | length 10.3
  Top Layer w0.254: R17.2@119.316,69.266 122.483,69.266 123.63,68.119 127.495,68.119 P5.10@128.626,69.25
NetP5_11: P5.11 R18.1 | length 14.3
  Top Layer w0.254: R18.1@112.458,66.692 112.806,67.04 112.831,67.04 113.262,67.47 113.438,67.47 113.439,67.471 121.057,67.471 121.819,66.71 P5.11@126.086,66.71
NetP5_12: P5.12 R19.2 | length 10.2
  Top Layer w0.254: R19.2@119.329,66.667 119.329,66.642 120.392,65.579 127.495,65.579 P5.12@128.626,66.71
NetP5_13: P5.13 R20.1 | length 6.8
  Top Layer w0.254: R20.1@119.329,64.186 119.345,64.17 P5.13@126.086,64.17
NetP9_1: P9.1 R64.1 | length 16.4
  Top Layer w0.254: R64.1@69.215,21.247 69.215,11.76 71.907,9.068 74.981,9.068 P9.1@75.006,9.042
NetP9_2: P9.2 R78.2 | length 17.4
  Top Layer w0.254: R78.2@70.764,21.247 70.764,11.811 71.882,10.693 75.971,10.693 77.546,9.119 P9.2@77.546,9.042
NetQ1_4: Q1.4 Q2.3 R5.2 TP2.1 | length 21.6
  Top Layer w0.254: v1(55.474,76.073) 56.413,76.073 Q1.4@56.439,76.048 ; R5.2@67.031,78.956 66.929,79.057 TP2.1@66.929,80.569 66.992,80.569 68.186,81.763 v1(68.25,81.763) 69.015,82.527 69.015,82.901 Q2.3@69.273,83.16
  L3 w0.254: v1(55.474,76.073) 61.392,81.991 67.901,81.991 68.129,81.763 v1(68.25,81.763)
NetQ9_2: Q9.2 R97.2 R99.2 | length 3.7
  Top Layer w0.254: Q9.2@84.232,63.5 84.937,63.5 85.392,63.955 85.392,63.98 85.74,64.328 R99.2@85.765,64.328 R97.2@85.765,66.141
NetQ9_3: Q9.3 R88.2 | length 2.1
  Top Layer w0.254: R88.2@84.01,66.116 83.987,66.093 83.987,65.111 84.232,64.866 Q9.3@84.232,64.15
NetQ9_5: Q9.5 R93.2 R100.1 | length 5.8
  Top Layer w0.254: R100.1@80.781,65.954 R93.2@80.781,64.328 81.127,64.674 82.96,64.674 83.109,64.525 83.109,63.708 82.901,63.5 82.51,63.5 82.451,63.559 Q9.5@82.392,63.5
NetQ9_6: Q9.6 R100.2 | length 7.5
  Top Layer w0.254: R100.2@80.781,67.741 80.806,67.741 81.586,66.962 81.586,65.429 81.796,65.219 83.062,65.219 83.566,64.715 83.566,63.348 83.033,62.814 Q9.6@82.652,62.814 ; Q9.6@82.392,62.85 Q9.6@82.453,62.911
NetQ10_3: Q10.3 R84.2 | length 2.1
  Top Layer w0.254: R84.2@72.314,13.094 72.349,13.129 73.268,13.129 73.635,13.496 73.83,13.496 Q10.3@74.103,13.769
NetR9_1: R9.1 SW1.1 SW1.2 | length 10.4
  Top Layer w0.254: R9.1@108.28,79.794 108.305,79.794 109.455,80.944 SW1.1@111.685,80.944 SW1.2@118.185,80.944
NetR21_2: R21.2 R66.1 | length 34.1
  Top Layer w0.508: R66.1@79.667,26.137 79.68,26.149 81.597,26.149 81.636,26.111 v1(81.636,26.162) ; v1(107.594,37.77) R21.2@108.801,37.77
  Bottom Layer w0.508: v1(81.636,26.162) 81.845,26.162 84.366,28.683 84.366,28.892 91.948,36.474 106.299,36.474 v1(107.594,37.77)
NetR50_1: R50.1 R56.2 | length 2.6
  Top Layer w0.254: R56.2@116.243,58.471 116.243,58.496 116.591,58.844 116.871,58.844 118.11,60.084 R50.1@118.135,60.084
NetR61_2: R61.2 R79.2 U3.8 | length 6.6
  Top Layer w0.254: U3.8@103.433,44.526 103.497,44.59 105.385,44.59 106.879,46.084 106.904,46.084 107.252,46.432 R61.2@107.252,46.457 107.277,46.482 R79.2@107.277,48.387
NetR62_1: R62.1 U3.1 | length 2.4
  Top Layer w0.254: R62.1@95.517,44.526 U3.1@97.888,44.526
NetR65_1: R65.1 U3.4 | length 2.4
  Top Layer w0.254: R65.1@95.517,40.64 95.593,40.716 U3.4@97.888,40.716
NetR81_2: R81.2 U2.7 | length 5.7
  Top Layer w0.254: R81.2@102.222,60.579 103.208,60.579 104.267,59.52 104.267,58.318 104.927,57.658 U2.7@106.007,57.658
NetR82_2: R82.2 R85.1 U5.5 | length 4.8
  Top Layer w0.254: R85.1@90.84,18.021 R82.2@92.491,18.021 92.491,16.353 91.983,15.845 U5.5@91.983,15.117
NetR105_1: R105.1 R106.1 | length 1.7
  Top Layer w0.254: R105.1@84.287,17.932 R106.1@84.287,19.66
